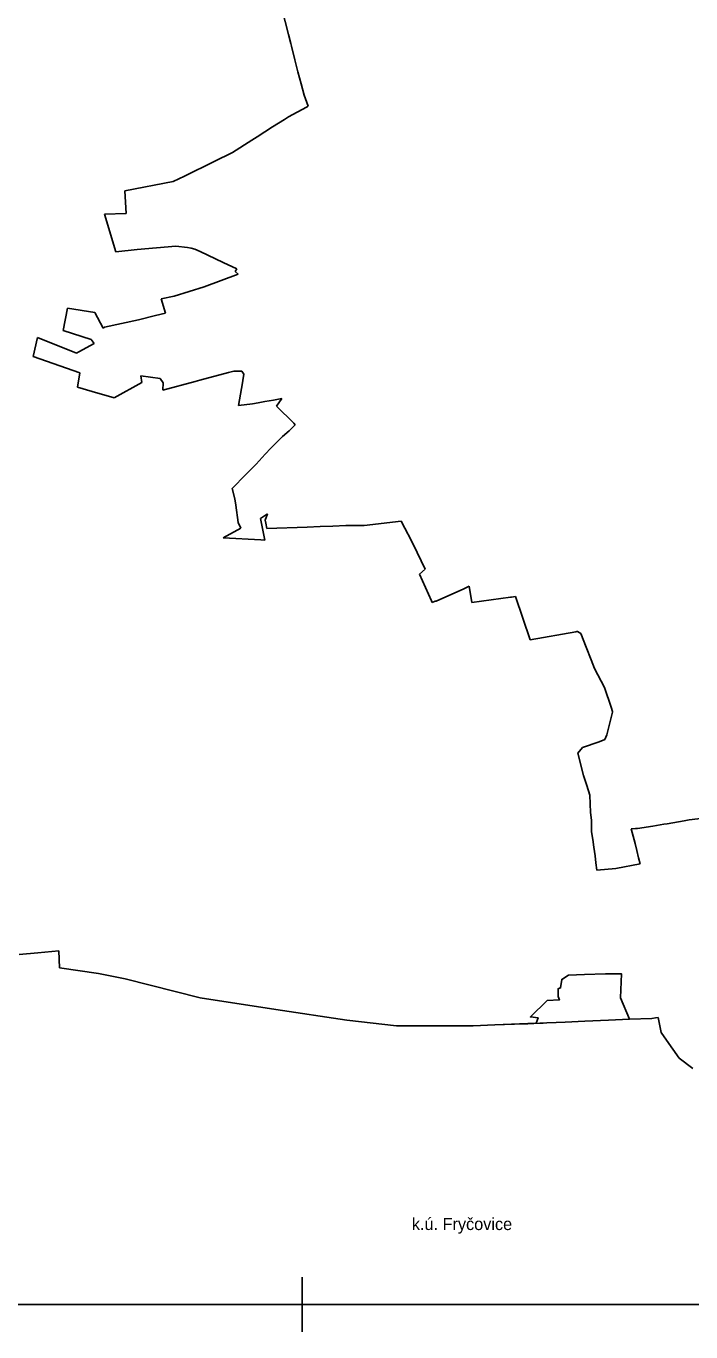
# Model space of a CAD drawing. Extents: x -478440 to -472455, y -1118045 to -1113755.
# Drawn here: x -477154 to -476061, y -1118045 to -1115899 of the extents above; entities that cross this region are included whole.
import ezdxf

# ---------------------------------------------------------------- set-up
doc = ezdxf.new("R2010")
doc.units = 0
for name, color, linetype in [('hranice kú', 7, 'Continuous'), ('Implicitní', 7, 'Continuous'), ('ObPÚ', 7, 'Continuous'), ('okolní k_ú_', 7, 'Continuous')]:
    doc.layers.add(name, color=color, linetype=linetype)

msp = doc.modelspace()

# ---------------------------------------------------------------- linework, layer by layer
at = {"layer": 'hranice kú'}
for p, q in [((-477165.8, -1117424.6), (-477134.7, -1117422.1)), ((-477134.7, -1117422.1), (-477100.4, -1117419)), ((-477100.4, -1117419), (-477099.3, -1117446.8)), ((-477099.3, -1117446.8), (-477035.2, -1117455.8)), ((-477035.2, -1117455.8), (-476991.4, -1117464.9)), ((-476991.4, -1117464.9), (-476867.7, -1117495.9)), ((-476867.7, -1117495.9), (-476743.2, -1117515.4)), ((-476743.2, -1117515.4), (-476626.6, -1117532.5)), ((-476626.6, -1117532.5), (-476544.9, -1117542)), ((-476161.9, -1117531.2), (-476125.1, -1117529.7)), ((-476125.1, -1117529.7), (-476118.9, -1117528.8)), ((-476118.9, -1117528.8), (-476114.9, -1117528.2)), ((-476114.9, -1117528.2), (-476109.7, -1117553.1)), ((-476544.9, -1117542), (-476419.1, -1117542)), ((-476419.1, -1117542), (-476383.4, -1117540.4)), ((-476383.4, -1117540.4), (-476335, -1117538.6)), ((-476109.7, -1117553.1), (-476101, -1117565.5)), ((-476101, -1117565.5), (-476080.1, -1117595.4)), ((-476080.1, -1117595.4), (-476057.9, -1117611.9))]:
    msp.add_line(p, q, dxfattribs=at)
msp.add_lwpolyline([(-476335, -1117538.6), (-476331.3, -1117538.5), (-476328.9, -1117538.5), (-476309.5, -1117537.6), (-476304, -1117537.5), (-476297.9, -1117537.3), (-476282.7, -1117536.7), (-476267.7, -1117535.9), (-476235.2, -1117534.5), (-476196.6, -1117532.7), (-476161.9, -1117531.2)], dxfattribs=at)
at = {"layer": 'Implicitní'}
for p, q in [((-476700.1, -1117955.1), (-476700.1, -1118045.1)), ((-476700.1, -1117955.1), (-476700.1, -1118045.1)), ((-476700.1, -1117955.1), (-476700.1, -1118045.1)), ((-476700.1, -1117955.1), (-476700.1, -1118045.1)), ((-476700.1, -1117955.1), (-476700.1, -1118045.1)), ((-476700.1, -1117955.1), (-476700.1, -1118045.1)), ((-476700.1, -1117955.1), (-476700.1, -1118045.1)), ((-476700.1, -1117955.1), (-476700.1, -1118045.1)), ((-476700.1, -1117955.1), (-476700.1, -1118045.1)), ((-476700.1, -1117955.1), (-476700.1, -1118045.1)), ((-476700.1, -1117955.1), (-476700.1, -1118045.1)), ((-476700.1, -1117955.1), (-476700.1, -1118045.1)), ((-476655.1, -1118000.1), (-476745.1, -1118000.1)), ((-476655.1, -1118000.1), (-476745.1, -1118000.1)), ((-476655.1, -1118000.1), (-476745.1, -1118000.1)), ((-476655.1, -1118000.1), (-476745.1, -1118000.1)), ((-476655.1, -1118000.1), (-476745.1, -1118000.1)), ((-476655.1, -1118000.1), (-476745.1, -1118000.1)), ((-476655.1, -1118000.1), (-476745.1, -1118000.1)), ((-476655.1, -1118000.1), (-476745.1, -1118000.1)), ((-476655.1, -1118000.1), (-476745.1, -1118000.1)), ((-476655.1, -1118000.1), (-476745.1, -1118000.1)), ((-476655.1, -1118000.1), (-476745.1, -1118000.1)), ((-476655.1, -1118000.1), (-476745.1, -1118000.1))]:
    msp.add_line(p, q, dxfattribs=at)
msp.add_lwpolyline([(-478440.1, -1118000.1), (-472500.1, -1118000.1), (-472500.1, -1113800.1), (-478440.1, -1113800.1)], close=True, dxfattribs=at)
at = {"layer": 'ObPÚ'}
for p, q in [((-476733.6, -1115870.1), (-476722.5, -1115912.6)), ((-476722.5, -1115912.6), (-476733.6, -1115870.1)), ((-476722.5, -1115912.6), (-476718.9, -1115927.6)), ((-476718.9, -1115927.6), (-476722.5, -1115912.6)), ((-476718.9, -1115927.6), (-476717.6, -1115931.8)), ((-476717.6, -1115931.8), (-476718.9, -1115927.6)), ((-476717.6, -1115931.8), (-476712, -1115954.3)), ((-476712, -1115954.3), (-476717.6, -1115931.8)), ((-476712, -1115954.3), (-476707.2, -1115973.9)), ((-476707.2, -1115973.9), (-476712, -1115954.3)), ((-476707.2, -1115973.9), (-476701.9, -1115993.5)), ((-476701.9, -1115993.5), (-476707.2, -1115973.9)), ((-476701.9, -1115993.5), (-476696.8, -1116012.4)), ((-476696.8, -1116012.4), (-476701.9, -1115993.5)), ((-476693.2, -1116031.9), (-476722.5, -1116048.2)), ((-476722.5, -1116048.2), (-476693.2, -1116031.9)), ((-476696.8, -1116012.4), (-476690.2, -1116030.3)), ((-476690.2, -1116030.3), (-476696.8, -1116012.4)), ((-476690.2, -1116030.3), (-476693.2, -1116031.9)), ((-476693.2, -1116031.9), (-476690.2, -1116030.3)), ((-476729.3, -1116052.3), (-476749, -1116064.6)), ((-476749, -1116064.6), (-476729.3, -1116052.3)), ((-476722.5, -1116048.2), (-476729.3, -1116052.3)), ((-476729.3, -1116052.3), (-476722.5, -1116048.2)), ((-476749, -1116064.6), (-476774.1, -1116081.1)), ((-476774.1, -1116081.1), (-476749, -1116064.6)), ((-476782.8, -1116086.5), (-476815, -1116106.6)), ((-476815, -1116106.6), (-476782.8, -1116086.5)), ((-476774.1, -1116081.1), (-476782.8, -1116086.5)), ((-476782.8, -1116086.5), (-476774.1, -1116081.1)), ((-476815, -1116106.6), (-476845, -1116121.3)), ((-476845, -1116121.3), (-476815, -1116106.6)), ((-476845, -1116121.3), (-476893.9, -1116145.4)), ((-476893.9, -1116145.4), (-476845, -1116121.3)), ((-476912.4, -1116154.5), (-476991.9, -1116169.5)), ((-476991.9, -1116169.5), (-476912.4, -1116154.5)), ((-476893.9, -1116145.4), (-476912.4, -1116154.5)), ((-476912.4, -1116154.5), (-476893.9, -1116145.4)), ((-476991.9, -1116169.5), (-476989.8, -1116206.9)), ((-476989.8, -1116206.9), (-476991.9, -1116169.5)), ((-476989.8, -1116206.9), (-477025, -1116207.7)), ((-477025, -1116207.7), (-476989.8, -1116206.9)), ((-477025, -1116207.7), (-477006.7, -1116269.7)), ((-477006.7, -1116269.7), (-477025, -1116207.7)), ((-477006.7, -1116269.7), (-476971.6, -1116265.9)), ((-476971.6, -1116265.9), (-477006.7, -1116269.7)), ((-476971.6, -1116265.9), (-476908, -1116260.7)), ((-476908, -1116260.7), (-476971.6, -1116265.9)), ((-476908, -1116260.7), (-476888.6, -1116262.8)), ((-476888.6, -1116262.8), (-476908, -1116260.7)), ((-476888.6, -1116262.8), (-476882.7, -1116264.1)), ((-476882.7, -1116264.1), (-476888.6, -1116262.8)), ((-476882.7, -1116264.1), (-476876.9, -1116265.5)), ((-476876.9, -1116265.5), (-476882.7, -1116264.1)), ((-476876.9, -1116265.5), (-476867.7, -1116269.2)), ((-476867.7, -1116269.2), (-476876.9, -1116265.5)), ((-476867.7, -1116269.2), (-476830.3, -1116287.4)), ((-476830.3, -1116287.4), (-476867.7, -1116269.2)), ((-476830.3, -1116287.4), (-476807.4, -1116297.7)), ((-476807.4, -1116297.7), (-476830.3, -1116287.4)), ((-476805.2, -1116306.6), (-476861.3, -1116327.5)), ((-476861.3, -1116327.5), (-476805.2, -1116306.6)), ((-476807.4, -1116297.7), (-476810.1, -1116302.4)), ((-476810.1, -1116302.4), (-476807.4, -1116297.7)), ((-476810.1, -1116302.4), (-476805.2, -1116306.6)), ((-476805.2, -1116306.6), (-476810.1, -1116302.4)), ((-476861.3, -1116327.5), (-476910.6, -1116343)), ((-476910.6, -1116343), (-476861.3, -1116327.5)), ((-476910.6, -1116343), (-476932, -1116347.3)), ((-476932, -1116347.3), (-476910.6, -1116343)), ((-476932, -1116347.3), (-476924.7, -1116370.9)), ((-476924.7, -1116370.9), (-476932, -1116347.3)), ((-477085.8, -1116362.2), (-477093.1, -1116399.3)), ((-477093.1, -1116399.3), (-477085.8, -1116362.2)), ((-477041.3, -1116369.7), (-477085.8, -1116362.2)), ((-477085.8, -1116362.2), (-477041.3, -1116369.7)), ((-477027.2, -1116395.1), (-477041.3, -1116369.7)), ((-477041.3, -1116369.7), (-477027.2, -1116395.1)), ((-476941.2, -1116374.5), (-476969.4, -1116381.7)), ((-476969.4, -1116381.7), (-476941.2, -1116374.5)), ((-476924.7, -1116370.9), (-476941.2, -1116374.5)), ((-476941.2, -1116374.5), (-476924.7, -1116370.9)), ((-477025, -1116393.9), (-477027.2, -1116395.1)), ((-477027.2, -1116395.1), (-477025, -1116393.9)), ((-476969.4, -1116381.7), (-477025, -1116393.9)), ((-477025, -1116393.9), (-476969.4, -1116381.7)), ((-477135.5, -1116410.9), (-477142.5, -1116441.9)), ((-477142.5, -1116441.9), (-477135.5, -1116410.9)), ((-477071.5, -1116436.2), (-477135.5, -1116410.9)), ((-477135.5, -1116410.9), (-477071.5, -1116436.2)), ((-477093.1, -1116399.3), (-477046.9, -1116414)), ((-477046.9, -1116414), (-477093.1, -1116399.3)), ((-477046.9, -1116414), (-477042.3, -1116420.6)), ((-477042.3, -1116420.6), (-477046.9, -1116414)), ((-477067.7, -1116434.3), (-477071.5, -1116436.2)), ((-477071.5, -1116436.2), (-477067.7, -1116434.3)), ((-477042.3, -1116420.6), (-477067.7, -1116434.3)), ((-477067.7, -1116434.3), (-477042.3, -1116420.6)), ((-477142.5, -1116441.9), (-477065.9, -1116469)), ((-477065.9, -1116469), (-477142.5, -1116441.9)), ((-477065.9, -1116469), (-477069.7, -1116492.4)), ((-477069.7, -1116492.4), (-477065.9, -1116469)), ((-476964.1, -1116484.6), (-476965.6, -1116473.9)), ((-476965.6, -1116473.9), (-476933.8, -1116478.3)), ((-476933.8, -1116478.3), (-476965.6, -1116473.9)), ((-476965.6, -1116473.9), (-476964.1, -1116484.6)), ((-476933.8, -1116478.3), (-476928.9, -1116485.4)), ((-476928.9, -1116485.4), (-476933.8, -1116478.3)), ((-476929.1, -1116497.1), (-476875.9, -1116482.9)), ((-476875.9, -1116482.9), (-476929.1, -1116497.1)), ((-476875.9, -1116482.9), (-476868.6, -1116480.9)), ((-476868.6, -1116480.9), (-476875.9, -1116482.9)), ((-476868.6, -1116480.9), (-476821.4, -1116468.2)), ((-476821.4, -1116468.2), (-476868.6, -1116480.9)), ((-476821.4, -1116468.2), (-476812.4, -1116465.8)), ((-476812.4, -1116465.8), (-476821.4, -1116468.2)), ((-476812.4, -1116465.8), (-476799.2, -1116466)), ((-476799.2, -1116466), (-476812.4, -1116465.8)), ((-476796, -1116471.1), (-476799.6, -1116491.5)), ((-476799.6, -1116491.5), (-476796, -1116471.1)), ((-476799.2, -1116466), (-476796, -1116471.1)), ((-476796, -1116471.1), (-476799.2, -1116466)), ((-477069.7, -1116492.4), (-477045.5, -1116499.5)), ((-477045.5, -1116499.5), (-477069.7, -1116492.4)), ((-477045.5, -1116499.5), (-477009.3, -1116510.1)), ((-477009.3, -1116510.1), (-477045.5, -1116499.5)), ((-477009.3, -1116510.1), (-476964.1, -1116484.6)), ((-476964.1, -1116484.6), (-477009.3, -1116510.1)), ((-476928.9, -1116485.4), (-476929.1, -1116497.1)), ((-476929.1, -1116497.1), (-476928.9, -1116485.4)), ((-476800.1, -1116494.5), (-476805, -1116522.7)), ((-476805, -1116522.7), (-476800.1, -1116494.5)), ((-476799.6, -1116491.5), (-476800.1, -1116494.5)), ((-476800.1, -1116494.5), (-476799.6, -1116491.5)), ((-476805, -1116522.7), (-476782.1, -1116519.5)), ((-476782.1, -1116519.5), (-476805, -1116522.7)), ((-476782.1, -1116519.5), (-476772.4, -1116517.8)), ((-476772.4, -1116517.8), (-476782.1, -1116519.5)), ((-476772.4, -1116517.8), (-476761.5, -1116515.9)), ((-476761.5, -1116515.9), (-476772.4, -1116517.8)), ((-476761.5, -1116515.9), (-476747.5, -1116513.5)), ((-476747.5, -1116513.5), (-476761.5, -1116515.9)), ((-476747.5, -1116513.5), (-476733.5, -1116511.1)), ((-476733.5, -1116511.1), (-476747.5, -1116513.5)), ((-476733.5, -1116511.1), (-476742.3, -1116523.7)), ((-476742.3, -1116523.7), (-476733.5, -1116511.1)), ((-476742.3, -1116523.7), (-476713.9, -1116551.5)), ((-476713.9, -1116551.5), (-476742.3, -1116523.7)), ((-476721.7, -1116564.1), (-476732.4, -1116573.6)), ((-476732.4, -1116573.6), (-476721.7, -1116564.1)), ((-476711.5, -1116554), (-476721.7, -1116564.1)), ((-476721.7, -1116564.1), (-476711.5, -1116554)), ((-476713.9, -1116551.5), (-476711.5, -1116554)), ((-476711.5, -1116554), (-476713.9, -1116551.5)), ((-476744.3, -1116585.4), (-476751.5, -1116592.3)), ((-476751.5, -1116592.3), (-476744.3, -1116585.4)), ((-476732.4, -1116573.6), (-476744.3, -1116585.4)), ((-476744.3, -1116585.4), (-476732.4, -1116573.6)), ((-476760.8, -1116602.4), (-476776, -1116619)), ((-476776, -1116619), (-476760.8, -1116602.4)), ((-476751.5, -1116592.3), (-476760.8, -1116602.4)), ((-476760.8, -1116602.4), (-476751.5, -1116592.3)), ((-476778.8, -1116621.7), (-476792.7, -1116635.9)), ((-476792.7, -1116635.9), (-476778.8, -1116621.7)), ((-476776, -1116619), (-476778.8, -1116621.7)), ((-476778.8, -1116621.7), (-476776, -1116619)), ((-476792.7, -1116635.9), (-476815.5, -1116658.9)), ((-476815.5, -1116658.9), (-476792.7, -1116635.9)), ((-476815.5, -1116658.9), (-476811, -1116675.8)), ((-476811, -1116675.8), (-476815.5, -1116658.9)), ((-476811, -1116675.8), (-476809.5, -1116686)), ((-476809.5, -1116686), (-476811, -1116675.8)), ((-476809.5, -1116686), (-476805.4, -1116714.9)), ((-476805.4, -1116714.9), (-476809.5, -1116686)), ((-476805.4, -1116714.9), (-476800.8, -1116724.3)), ((-476800.8, -1116724.3), (-476805.4, -1116714.9)), ((-476768.5, -1116708.3), (-476757, -1116700.3)), ((-476757, -1116700.3), (-476768.5, -1116708.3)), ((-476761.5, -1116743.6), (-476768.5, -1116708.3)), ((-476768.5, -1116708.3), (-476761.5, -1116743.6)), ((-476757, -1116700.3), (-476761, -1116711)), ((-476761, -1116711), (-476757, -1116700.3)), ((-476761, -1116711), (-476760.1, -1116716.1)), ((-476760.1, -1116716.1), (-476761, -1116711)), ((-476760.1, -1116716.1), (-476758.5, -1116724.7)), ((-476758.5, -1116724.7), (-476760.1, -1116716.1)), ((-476628.4, -1116719.8), (-476598.3, -1116719.5)), ((-476598.3, -1116719.5), (-476628.4, -1116719.8)), ((-476598.3, -1116719.5), (-476537.2, -1116712.7)), ((-476537.2, -1116712.7), (-476598.3, -1116719.5)), ((-476537.2, -1116712.7), (-476531.3, -1116724.2)), ((-476531.3, -1116724.2), (-476537.2, -1116712.7)), ((-476800.8, -1116724.3), (-476830, -1116739.9)), ((-476830, -1116739.9), (-476800.8, -1116724.3)), ((-476830, -1116739.9), (-476768.1, -1116743.4)), ((-476768.1, -1116743.4), (-476830, -1116739.9)), ((-476758.5, -1116724.7), (-476692.1, -1116722.2)), ((-476692.1, -1116722.2), (-476758.5, -1116724.7)), ((-476692.1, -1116722.2), (-476670.8, -1116721.4)), ((-476670.8, -1116721.4), (-476692.1, -1116722.2)), ((-476670.8, -1116721.4), (-476649.6, -1116720.6)), ((-476649.6, -1116720.6), (-476670.8, -1116721.4)), ((-476649.6, -1116720.6), (-476628.4, -1116719.8)), ((-476628.4, -1116719.8), (-476649.6, -1116720.6)), ((-476531.3, -1116724.2), (-476521.1, -1116744)), ((-476521.1, -1116744), (-476531.3, -1116724.2)), ((-476768.1, -1116743.4), (-476761.5, -1116743.6)), ((-476761.5, -1116743.6), (-476768.1, -1116743.4)), ((-476521.1, -1116744), (-476511, -1116763.8)), ((-476511, -1116763.8), (-476521.1, -1116744)), ((-476511, -1116763.8), (-476498, -1116791.6)), ((-476498, -1116791.6), (-476511, -1116763.8)), ((-476498, -1116791.6), (-476507.2, -1116799.7)), ((-476507.2, -1116799.7), (-476498, -1116791.6)), ((-476507.2, -1116799.7), (-476487.6, -1116843.5)), ((-476487.6, -1116843.5), (-476507.2, -1116799.7)), ((-476453.9, -1116832.5), (-476435.3, -1116824.4)), ((-476435.3, -1116824.4), (-476453.9, -1116832.5)), ((-476435.3, -1116824.4), (-476428.7, -1116821.1)), ((-476428.7, -1116821.1), (-476435.3, -1116824.4)), ((-476428.7, -1116821.1), (-476425.6, -1116819.5)), ((-476425.6, -1116819.5), (-476428.7, -1116821.1)), ((-476425.6, -1116819.5), (-476420.9, -1116846)), ((-476420.9, -1116846), (-476425.6, -1116819.5)), ((-476487.6, -1116843.5), (-476486.3, -1116846.5)), ((-476486.3, -1116846.5), (-476487.6, -1116843.5)), ((-476486.3, -1116846.5), (-476481.2, -1116844.2)), ((-476481.2, -1116844.2), (-476486.3, -1116846.5)), ((-476481.2, -1116844.2), (-476479.8, -1116844)), ((-476479.8, -1116844), (-476481.2, -1116844.2)), ((-476479.8, -1116844), (-476453.9, -1116832.5)), ((-476453.9, -1116832.5), (-476479.8, -1116844)), ((-476420.9, -1116846), (-476357.6, -1116837.7)), ((-476357.6, -1116837.7), (-476420.9, -1116846)), ((-476357.6, -1116837.7), (-476355.8, -1116837.4)), ((-476355.8, -1116837.4), (-476357.6, -1116837.7)), ((-476355.8, -1116837.4), (-476349.2, -1116836.4)), ((-476349.2, -1116836.4), (-476355.8, -1116837.4)), ((-476349.2, -1116836.4), (-476325, -1116907.8)), ((-476325, -1116907.8), (-476349.2, -1116836.4)), ((-476325, -1116907.8), (-476249.9, -1116894.2)), ((-476249.9, -1116894.2), (-476325, -1116907.8)), ((-476249.9, -1116894.2), (-476248.4, -1116893.9)), ((-476248.4, -1116893.9), (-476249.9, -1116894.2)), ((-476248.4, -1116893.9), (-476247.2, -1116894.1)), ((-476247.2, -1116894.1), (-476248.4, -1116893.9)), ((-476247.2, -1116894.1), (-476242, -1116897.4)), ((-476242, -1116897.4), (-476247.2, -1116894.1)), ((-476242, -1116897.4), (-476233.2, -1116919.5)), ((-476233.2, -1116919.5), (-476242, -1116897.4)), ((-476233.2, -1116919.5), (-476224.8, -1116940.7)), ((-476224.8, -1116940.7), (-476233.2, -1116919.5)), ((-476224.8, -1116940.7), (-476219.2, -1116954.7)), ((-476219.2, -1116954.7), (-476224.8, -1116940.7)), ((-476219.2, -1116954.7), (-476202.8, -1116986)), ((-476202.8, -1116986), (-476219.2, -1116954.7)), ((-476202.8, -1116986), (-476192.2, -1117018.3)), ((-476192.2, -1117018.3), (-476202.8, -1116986)), ((-476192.2, -1117018.3), (-476190, -1117025.4)), ((-476190, -1117025.4), (-476192.2, -1117018.3)), ((-476190, -1117025.4), (-476189.6, -1117026.5)), ((-476189.6, -1117026.5), (-476190, -1117025.4)), ((-476211.7, -1117075.4), (-476239.4, -1117084.7)), ((-476239.4, -1117084.7), (-476211.7, -1117075.4)), ((-476202.6, -1117071.3), (-476211.7, -1117075.4)), ((-476211.7, -1117075.4), (-476202.6, -1117071.3)), ((-476237.3, -1117130.7), (-476232.2, -1117147)), ((-476232.2, -1117147), (-476237.3, -1117130.7)), ((-476232.2, -1117147), (-476227.2, -1117162.7)), ((-476227.2, -1117162.7), (-476232.2, -1117147)), ((-476227.2, -1117162.7), (-476226.2, -1117191.6)), ((-476226.2, -1117191.6), (-476227.2, -1117162.7)), ((-476226.2, -1117191.6), (-476224.6, -1117203.8)), ((-476224.6, -1117203.8), (-476226.2, -1117191.6)), ((-476224.6, -1117203.8), (-476224.2, -1117223.3)), ((-476224.2, -1117223.3), (-476224.6, -1117203.8)), ((-476123.4, -1117213.9), (-476105.5, -1117210.8)), ((-476105.5, -1117210.8), (-476123.4, -1117213.9)), ((-476105.5, -1117210.8), (-476099.8, -1117209.8)), ((-476099.8, -1117209.8), (-476105.5, -1117210.8)), ((-476099.8, -1117209.8), (-476072.1, -1117205)), ((-476072.1, -1117205), (-476099.8, -1117209.8)), ((-476072.1, -1117205), (-476063.9, -1117203.5)), ((-476063.9, -1117203.5), (-476072.1, -1117205)), ((-476063.9, -1117203.5), (-476001.4, -1117196.3)), ((-476001.4, -1117196.3), (-476063.9, -1117203.5)), ((-476224.2, -1117223.3), (-476222.4, -1117235.9)), ((-476222.4, -1117235.9), (-476224.2, -1117223.3)), ((-476159.1, -1117218.3), (-476152.2, -1117217.5)), ((-476152.2, -1117217.5), (-476159.1, -1117218.3)), ((-476155.9, -1117230.3), (-476159.1, -1117218.3)), ((-476159.1, -1117218.3), (-476155.9, -1117230.3)), ((-476152.8, -1117242.2), (-476155.9, -1117230.3)), ((-476155.9, -1117230.3), (-476152.8, -1117242.2)), ((-476152.2, -1117217.5), (-476148.9, -1117217.5)), ((-476148.9, -1117217.5), (-476152.2, -1117217.5)), ((-476148.9, -1117217.5), (-476123.4, -1117213.9)), ((-476123.4, -1117213.9), (-476148.9, -1117217.5)), ((-476222.4, -1117235.9), (-476220.5, -1117248.5)), ((-476220.5, -1117248.5), (-476222.4, -1117235.9)), ((-476220.5, -1117248.5), (-476218.4, -1117262.5)), ((-476218.4, -1117262.5), (-476220.5, -1117248.5)), ((-476149.8, -1117253.9), (-476152.8, -1117242.2)), ((-476152.8, -1117242.2), (-476149.8, -1117253.9)), ((-476147, -1117265.9), (-476149.8, -1117253.9)), ((-476149.8, -1117253.9), (-476147, -1117265.9)), ((-476218.4, -1117262.5), (-476217.2, -1117274.1)), ((-476217.2, -1117274.1), (-476218.4, -1117262.5)), ((-476217.2, -1117274.1), (-476215.6, -1117286.4)), ((-476215.6, -1117286.4), (-476217.2, -1117274.1)), ((-476184.5, -1117283.5), (-476144.3, -1117275.9)), ((-476144.3, -1117275.9), (-476184.5, -1117283.5)), ((-476144.3, -1117275.9), (-476147, -1117265.9)), ((-476147, -1117265.9), (-476144.3, -1117275.9)), ((-476215.6, -1117286.4), (-476184.5, -1117283.5)), ((-476184.5, -1117283.5), (-476215.6, -1117286.4)), ((-477165.8, -1117424.6), (-477134.7, -1117422.1)), ((-477134.7, -1117422.1), (-477100.4, -1117419)), ((-477100.4, -1117419), (-477099.3, -1117446.8)), ((-477099.3, -1117446.8), (-477035.2, -1117455.8)), ((-477035.2, -1117455.8), (-476991.4, -1117464.9)), ((-476991.4, -1117464.9), (-476867.7, -1117495.9)), ((-476867.7, -1117495.9), (-476743.2, -1117515.4)), ((-476743.2, -1117515.4), (-476626.6, -1117532.5)), ((-476626.6, -1117532.5), (-476544.9, -1117542)), ((-476161.9, -1117531.2), (-476125.1, -1117529.7)), ((-476125.1, -1117529.7), (-476118.9, -1117528.8)), ((-476118.9, -1117528.8), (-476114.9, -1117528.2)), ((-476114.9, -1117528.2), (-476109.7, -1117553.1)), ((-476544.9, -1117542), (-476419.1, -1117542)), ((-476419.1, -1117542), (-476383.4, -1117540.4)), ((-476383.4, -1117540.4), (-476315.2, -1117537.9)), ((-476109.7, -1117553.1), (-476101, -1117565.5)), ((-476101, -1117565.5), (-476080.1, -1117595.4)), ((-476080.1, -1117595.4), (-476057.9, -1117611.9))]:
    msp.add_line(p, q, dxfattribs=at)
for points in [[(-476189.6, -1117026.5), (-476198.9, -1117063.9), (-476202.6, -1117071.3)], [(-476202.6, -1117071.3), (-476198.9, -1117063.9), (-476189.6, -1117026.5)], [(-476239.4, -1117084.7), (-476247, -1117093.6), (-476237.3, -1117130.7)], [(-476237.3, -1117130.7), (-476247, -1117093.6), (-476239.4, -1117084.7)], [(-476315.2, -1117537.9), (-476312.2, -1117528.7), (-476324.8, -1117527.5), (-476297.2, -1117500.4), (-476277.2, -1117499.3), (-476279.2, -1117493.6), (-476279.2, -1117481), (-476276.8, -1117480.1), (-476275.2, -1117479.8), (-476273.2, -1117465.8), (-476262.3, -1117458.7), (-476236, -1117457.8), (-476201.6, -1117456.8), (-476175.1, -1117456.3), (-476176.6, -1117495.8), (-476161.9, -1117531.2)]]:
    msp.add_lwpolyline(points, dxfattribs=at)

# ---------------------------------------------------------------- texts
at = {"layer": 'okolní k_ú_'}
msp.add_text('k.ú. Fryčovice', height=20, rotation=359.9619, dxfattribs=at).set_placement((-476519.8, -1117877.6))

doc.saveas('drawing.dxf')
